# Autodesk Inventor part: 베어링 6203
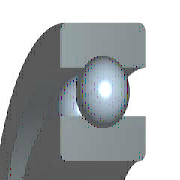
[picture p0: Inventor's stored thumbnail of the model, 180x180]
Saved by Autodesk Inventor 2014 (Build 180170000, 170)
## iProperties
IsCustomPart: 0
Company: 한국ATC센터
Created: 2015-11
Part Number: 베어링 6203
Material: 강철, 연강
Description: 깊은 그루브 볼 베어링
Document SubType Name: Modeling
Standard: KS B 2023
Designer: mdu
Standards Organization: KS
Language: ko-KR
Size Designation: 6203 - 17 x 40 x 12
Categories: <MemberInstance><Categories><Category DisplayName="샤프트 부품" InternalName="7f7aeb1f-a693-4053-b835-cee3144e0d98" Mnemonic="SHFT"><Category DisplayName="베어링" Inter
Density: 7.86 g/cm^3
Appearance: 크롬 - 광택
Mass: 58.8203 g
Surface Area: 64.3582 cm^2
Volume: 7.4835 cm^3
Author: mdu
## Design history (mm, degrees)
sketch "스케치" dims "d0" = 5.98 (= -0.26 x WD + 0.26 x BD)
  geometry: L1 (3.01, 14.25)-(8.99, 14.25); L2 (6, 14.25)-(6, 11.26); L3 (6, 14.25)-(6, 17.24); L4 (3.778, 12.249)-(0, 12.249); L5 (0, 8.5)-(12, 8.5); L6 (3.778, 16.251)-(0, 16.251); L7 (0, 20)-(12, 20); L8 (12, 8.5)-(12, 12.249); L9 (8.222, 12.249)-(12, 12.249); L10 (8.222, 16.251)-(12, 16.251); L11 (12, 20)-(12, 16.251); L12 (-1.4, 0)-(8.4, 0) reference; L13 (0, -0.3)-(0, 5.3) reference
  constraints: 22 end point, 4 point on line, 2 collinear, 2 perpendicular, 2 symmetric about line, 1 midpoint, 1 parallel, 14 other
  dimensions: "d9" = 17 diameter of L5 L12 (= WD); "d11" = 40 diameter of L7 L12 (= BD); "d12" = 12 distance between parallel lines of L8 L13 (= KB); "d13" = 24.498 diameter of L9 L12 (= 0.326 x BD + 0.674 x WD)
revolve "본체" stored, may be unused: angle "d6" = 90 deg
revolve "볼" stored, may be unused: angle "d7" = 90 deg
pattern_circular "IDS_ARRAYBALL[SIMPL:T]" dims angle "d3" = 360 deg
body "Solid1"
fillet "모깎기1" dims "d1" = 0.6 (= KRS)
other parameters: "WD" = 17 [user parameter; used in 5 equation terms], "BD" = 40 [user parameter; used in 5 equation terms], "KB" = 12 [user parameter; used in 1 equation term], "KRS" = 0.6 [user parameter; used in 1 equation term], "d4" = 0, "d5" = 0, "d8" = 0, "d14" = 0, "d15" = 0, "BBA" = 0 [user parameter], "BC0" = 4750000 [user parameter], "BC" = 9560000 [user parameter], "WR" = 8.5 (= 0.5 x WD) [user parameter]
